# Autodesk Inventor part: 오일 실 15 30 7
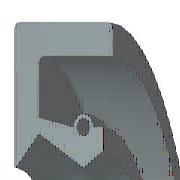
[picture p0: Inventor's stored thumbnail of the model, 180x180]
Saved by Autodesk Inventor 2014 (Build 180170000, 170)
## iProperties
IsCustomPart: 1
Created: 2012-02
Part Number: 오일 실 15 30 7
Material: 고무
Description: 오일-실
Document SubType Name: Modeling
Standard: KS B 2804
Designer: mduedu
Standards Organization: KS
Language: ko-KR
Size Designation: D - 15 30 7
Categories: <MemberInstance><Categories><Category DisplayName="샤프트 부품" InternalName="7f7aeb1f-a693-4053-b835-cee3144e0d98" Mnemonic="SHFT"><Category DisplayName="실링" Intern
Density: 0.93 g/cm^3
Appearance: 고무 - 검은색 - 버전 1.1
Author: mduedu
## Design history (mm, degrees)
revolve "본체" stored, may be unused: angle "d17" = 90 deg
revolve "스프링1" stored, may be unused: angle "d18" = 90 deg
body "Solid1"
sketch "스케치1"
  geometry: L1 (0, 15)-(7, 15); L2 (7, 13.25)-(1.75, 13.25); L3 (1.75, 9.25)-(4.9, 7.5); L4 (4.9, 7.5)-(0, 7.5); L5 (0, 0)-(9.586, 0) reference; L6 (4.9, 7.5)-(6.3, 8.375); L7 (0, 18)-(0, -3) reference; L8 (-1.941, 0)-(11.507, 0) reference; L9 (4.2, 9.6)-(1.75, 10.09); L10 (1.75, 10.09)-(1.75, 13.25); L11 (0, 15)-(0, 7.588); L12 (4.9, 7.5)-(0, 7.5); L13 (1.75, 9.25)-(0.152, 7.528); L14 (7, 15)-(7, 13.25); L15 (5.6, 9.6)-(6.3, 9.6); L16 (6.3, 9.6)-(6.3, 8.375); C1 r 0.455 at (4.9, 9.6); A1 r 0.7 centre (4.9, 9.6) between (5.6, 9.6) and (4.2, 9.6); A2 r 0.088 centre (0.088, 7.588) between (0, 7.588) and (0.152, 7.528); 1 further point
  constraints: 28 end point, 5 horizontal alignment, 5 point on line, 4 point on circle, 4 vertical alignment, 3 centre point, 3 tangent, 2 collinear, 2 horizontal, 2 perpendicular, 1 coincident, 1 parallel
  dimensions: "d0" = 30 diameter of L1 L5 (= SD2); "d1" = 1.75 distance of L1.end L2.start (= SD); "d2" = 0.91 diameter of C1 (= SPDI); "d3" = 1.4 diameter of A1 (= SPDA); "d4" = 15 diameter of L3.end L5 (= NND); "d5" = 18.5 diameter of L3.start L5 (= TKDM); "d7" = 20.18 diameter of L9.end L5 (= TKDM + 0.24 x SWDT); "d8" = 1.75 distance between parallel lines of L11 L10 (= SD); "d9" = 4.9 distance from line of L11 C1.centre (= SPDST); "d10" = 19.2 diameter of C1.centre L5 (= HLDM); "d11" = 0.0875 radius of A2 (= 0.25 x LAB); "d12" = 6.3 distance between parallel lines of L11 L16 (= SDI); "d13" = 16.75 diameter of L6.end L5 (= ABDM); "d14" = 7 distance from line of L11 L1.end (= SWDT)
fillet "모깎기1" dims "d6" = 0.3 (= RR)
other parameters: "SD2" = 30 [user parameter; used in 1 equation term], "SWDT" = 7 [user parameter; used in 2 equation terms], "RR" = 0.3 [user parameter; used in 1 equation term], "SD" = 1.75 [user parameter; used in 2 equation terms], "NND" = 15 [user parameter; used in 1 equation term], "SPDA" = 1.4 [user parameter; used in 1 equation term], "SPDI" = 0.91 [user parameter; used in 1 equation term], "TKDM" = 18.5 [user parameter; used in 2 equation terms], "HLDM" = 19.2 [user parameter; used in 1 equation term], "ABDM" = 16.75 [user parameter; used in 1 equation term], "SDI" = 6.3 [user parameter; used in 1 equation term], "SPDST" = 4.9 [user parameter; used in 1 equation term], "LAB" = 0.35 [user parameter; used in 1 equation term], "d15" = 0, "d16" = 0, "d19" = 0
